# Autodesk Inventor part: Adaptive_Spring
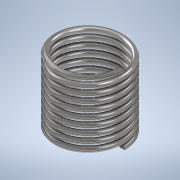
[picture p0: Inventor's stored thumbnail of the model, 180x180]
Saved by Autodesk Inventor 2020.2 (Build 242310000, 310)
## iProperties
Created: 2020-01
Part Number: Adaptive_Spring
Material: Iron, Malleable
Document SubType Name: Modeling
Designer: thira
Density: 7.15 g/cm^3
Appearance: Semi-Polished
Author: thira
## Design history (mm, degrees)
sketch "Sketch1"
  geometry: C1 r 100 at (0, 0); 1 further point
  constraints: 1 centre point, 1 coincident
  dimensions: "d0" = 200 diameter of C1
extrude "Extrusion1" new body sketch "Sketch1" taper "d2" = 0 deg; distance "Height" = 200
sketch "Sketch2"
  geometry: L1 (100, 200)-(100, 0) reference; L2 (100, 0)-(-100, 0) reference; L3 (-100, 0)-(-100, 200) reference; L4 (-100, 200)-(100, 200) reference; C1 r 7.5 at (92.5, 0); 1 further point
  constraints: 1 centre point, 1 point on line, 1 tangent
  dimensions: "d3" = 15 diameter of C1
coil "Coil1" sketch "Sketch2" pitch "d4" = 20 (= 0.1 x Height); turns "d6" = 1; dims "d5" = 200 (= Height), "d7" = 0, angle "d8" = 90 deg, angle "d9" = 90 deg, "d10" = 0, "d11" = 0
body "Solid1"
node "Project Cut Edges1"
